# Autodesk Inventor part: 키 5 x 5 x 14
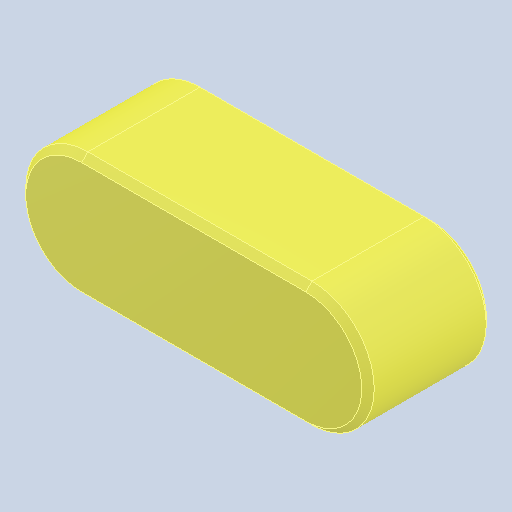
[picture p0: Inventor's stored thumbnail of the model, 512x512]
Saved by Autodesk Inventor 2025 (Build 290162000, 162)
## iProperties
Created: 2024-07
Part Number: 키 5 x 5 x 14
Material: 강철, 연강
Description: 키 및 해당 키홈
Document SubType Name: Modeling
Designer: 학생
Density: 7.85 g/cm^3
Appearance: 기본값
Author: jhkim
Sending System: Autodesk Inventor 2025
Preprocessor: ST-DEVELOPER v20
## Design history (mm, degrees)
feature "Solid1"
node "솔리드1"
